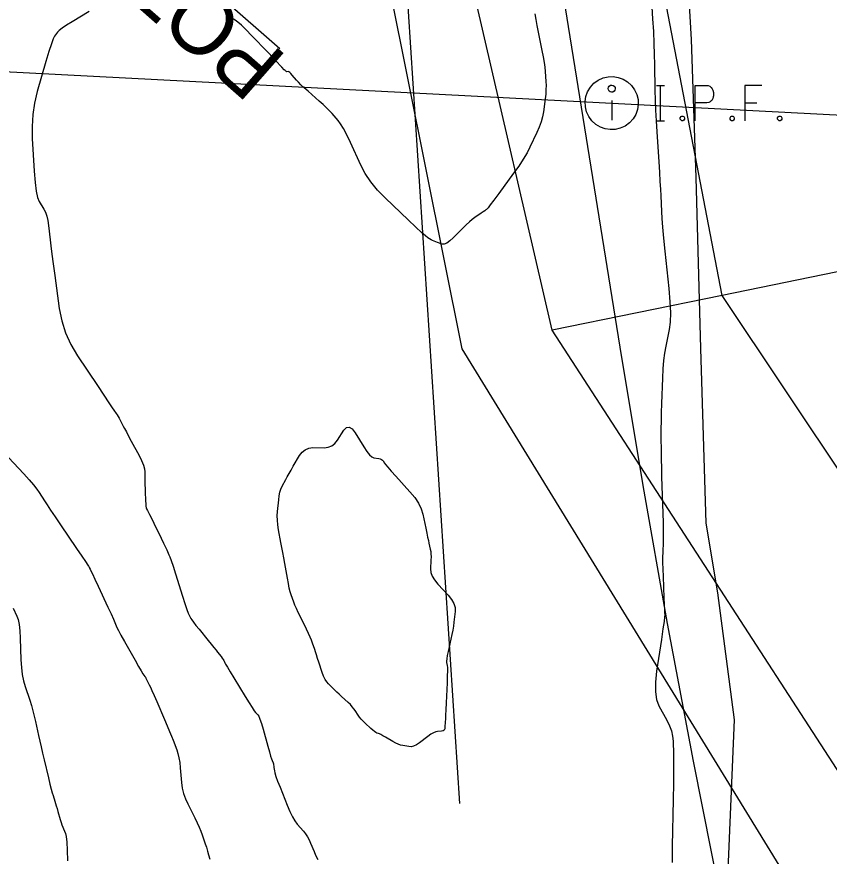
# Model space of a CAD drawing. Extents: x 2030588 to 2035216, y 462285 to 465007.
# Drawn here: x 2031207.57 to 2031244.28, y 464202.77 to 464240.7 of the extents above; entities that cross this region are included whole.
import ezdxf

# ---------------------------------------------------------------- set-up
doc = ezdxf.new("R2010")
doc.units = 0
for name, color, linetype in [('DT_P_Slope_Break_Line', 7, 'Continuous'), ('DT_X_Contour_Major', 7, 'Continuous'), ('DT_X_Contour_Minor', 7, 'Continuous'), ('DV_X_Property_Line', 7, 'Continuous'), ('GE_P_Alignment_100_Cardinal_Points', 7, 'Continuous'), ('MD_P_CONST_LIMITS', 7, 'Continuous'), ('RW_X_Esmt_SH', 7, 'Continuous'), ('SV_X_Break_Lines', 7, 'Continuous'), ('SV_X_Mon_Cells_Found', 7, 'Continuous'), ('VG_X_Tree_Line_Lt', 7, 'Continuous')]:
    doc.layers.add(name, color=color, linetype=linetype)

msp = doc.modelspace()

# ---------------------------------------------------------------- linework, layer by layer
at = {"layer": 'DT_P_Slope_Break_Line'}
for p, q in [((2031239.441, 464228.107), (2031234.605, 464253.315)), ((2031231.768, 464226.532), (2031225.918, 464251.764)), ((2031250.924, 464230.464), (2031239.441, 464228.107)), ((2031239.441, 464228.107), (2031231.768, 464226.532)), ((2031254.663, 464205.295), (2031239.441, 464228.107)), ((2031246.735, 464203.453), (2031231.768, 464226.532))]:
    msp.add_line(p, q, dxfattribs=at)
at = {"layer": 'DT_X_Contour_Major'}
msp.add_lwpolyline([(2031207.207, 464220.779), (2031207.892, 464220.039), (2031208.128, 464219.778), (2031208.322, 464219.552), (2031208.475, 464219.359), (2031208.587, 464219.2), (2031208.829, 464218.82), (2031208.942, 464218.646), (2031209.1, 464218.408), (2031209.302, 464218.106), (2031209.55, 464217.739), (2031210.269, 464216.677), (2031210.506, 464216.327), (2031210.676, 464216.076), (2031210.781, 464215.922), (2031210.819, 464215.866), (2031210.833, 464215.846), (2031210.839, 464215.837), (2031210.846, 464215.825), (2031210.855, 464215.808), (2031210.864, 464215.789), (2031210.892, 464215.731), (2031210.922, 464215.668), (2031210.991, 464215.521), (2031211.098, 464215.29), (2031211.245, 464214.976), (2031211.687, 464214.026), (2031211.833, 464213.711), (2031211.94, 464213.477), (2031212.008, 464213.325), (2031212.037, 464213.254), (2031212.063, 464213.173), (2031212.094, 464213.107), (2031212.167, 464212.969), (2031212.283, 464212.758), (2031212.441, 464212.475), (2031212.92, 464211.625), (2031213.079, 464211.343), (2031213.198, 464211.135), (2031213.277, 464211.001), (2031213.316, 464210.941), (2031213.366, 464210.88), (2031213.387, 464210.851), (2031213.412, 464210.81), (2031213.44, 464210.758), (2031213.472, 464210.694), (2031213.563, 464210.508), (2031213.61, 464210.408), (2031213.681, 464210.25), (2031213.777, 464210.033), (2031213.897, 464209.757), (2031214.252, 464208.941), (2031214.376, 464208.654), (2031214.482, 464208.403), (2031214.57, 464208.187), (2031214.639, 464208.008), (2031214.8, 464207.579), (2031214.856, 464207.407), (2031214.902, 464207.213), (2031214.938, 464206.997), (2031214.964, 464206.758), (2031215.02, 464206.093), (2031215.054, 464205.845), (2031215.111, 464205.601), (2031215.193, 464205.361), (2031215.299, 464205.125), (2031215.615, 464204.5), (2031215.725, 464204.276), (2031215.818, 464204.073), (2031215.894, 464203.89), (2031215.953, 464203.728), (2031216.089, 464203.323), (2031216.14, 464203.167), (2031216.19, 464202.999), (2031216.24, 464202.822), (2031216.29, 464202.634)], dxfattribs=at)
at = {"layer": 'DT_X_Contour_Minor'}
for points in [[(2031236.213, 464242.213), (2031236.306, 464240.613), (2031236.338, 464240.034), (2031236.363, 464239.496), (2031236.381, 464238.998), (2031236.391, 464238.542), (2031236.411, 464237.379), (2031236.422, 464236.934), (2031236.439, 464236.472), (2031236.463, 464235.993), (2031236.493, 464235.497), (2031236.582, 464234.15), (2031236.613, 464233.675), (2031236.638, 464233.26), (2031236.658, 464232.904), (2031236.673, 464232.609), (2031236.705, 464231.901), (2031236.723, 464231.589), (2031236.756, 464231.186), (2031236.802, 464230.69), (2031236.861, 464230.103), (2031237.038, 464228.415), (2031237.089, 464227.825), (2031237.108, 464227.321), (2031237.097, 464226.905), (2031237.053, 464226.575), (2031236.897, 464225.81), (2031236.843, 464225.505), (2031236.801, 464225.164), (2031236.769, 464224.786), (2031236.748, 464224.373), (2031236.707, 464223.222), (2031236.694, 464222.808), (2031236.686, 464222.428), (2031236.682, 464222.084), (2031236.683, 464221.775), (2031236.692, 464220.996), (2031236.697, 464220.683), (2031236.704, 464220.328), (2031236.714, 464219.931), (2031236.727, 464219.491), (2031236.765, 464218.261), (2031236.776, 464217.835), (2031236.782, 464217.479), (2031236.783, 464217.192), (2031236.779, 464216.976), (2031236.76, 464216.491), (2031236.756, 464216.287), (2031236.757, 464216.038), (2031236.764, 464215.743), (2031236.776, 464215.404), (2031236.816, 464214.44), (2031236.829, 464214.122), (2031236.84, 464213.892), (2031236.847, 464213.749), (2031236.851, 464213.693), (2031236.857, 464213.662), (2031236.849, 464213.584), (2031236.82, 464213.375), (2031236.77, 464213.035), (2031236.7, 464212.563), (2031236.485, 464211.13), (2031236.431, 464210.629), (2031236.431, 464210.201), (2031236.484, 464209.846), (2031236.591, 464209.563), (2031236.948, 464208.907), (2031237.065, 464208.664), (2031237.152, 464208.426), (2031237.207, 464208.194), (2031237.23, 464207.967), (2031237.251, 464207.37), (2031237.255, 464207.075), (2031237.254, 464206.637), (2031237.246, 464206.057), (2031237.232, 464205.333), (2031237.187, 464203.214), (2031237.185, 464202.479)], [(2031210.838, 464240.942), (2031210.082, 464240.475), (2031209.827, 464240.314), (2031209.632, 464240.181), (2031209.494, 464240.075), (2031209.415, 464239.997), (2031209.283, 464239.826), (2031209.221, 464239.707), (2031209.136, 464239.475), (2031209.026, 464239.132), (2031208.892, 464238.678), (2031208.502, 464237.318), (2031208.378, 464236.803), (2031208.299, 464236.277), (2031208.264, 464235.74), (2031208.274, 464235.192), (2031208.36, 464233.718), (2031208.398, 464233.218), (2031208.447, 464232.824), (2031208.509, 464232.536), (2031208.582, 464232.353), (2031208.793, 464232.007), (2031208.866, 464231.864), (2031208.926, 464231.692), (2031208.973, 464231.493), (2031209.008, 464231.266), (2031209.084, 464230.623), (2031209.119, 464230.341), (2031209.165, 464229.979), (2031209.223, 464229.537), (2031209.293, 464229.014), (2031209.495, 464227.513), (2031209.603, 464226.957), (2031209.777, 464226.416), (2031210.015, 464225.891), (2031210.319, 464225.381), (2031211.215, 464224.04), (2031211.514, 464223.593), (2031211.739, 464223.258), (2031211.889, 464223.034), (2031211.966, 464222.922), (2031212.07, 464222.773), (2031212.111, 464222.712), (2031212.154, 464222.641), (2031212.201, 464222.559), (2031212.25, 464222.466), (2031212.386, 464222.206), (2031212.447, 464222.09), (2031212.528, 464221.937), (2031212.629, 464221.748), (2031212.75, 464221.522), (2031213.1, 464220.87), (2031213.215, 464220.641), (2031213.297, 464220.441), (2031213.346, 464220.272), (2031213.363, 464220.132), (2031213.363, 464219.8), (2031213.364, 464219.671), (2031213.367, 464219.535), (2031213.37, 464219.392), (2031213.376, 464219.24), (2031213.391, 464218.826), (2031213.399, 464218.687), (2031213.409, 464218.579), (2031213.422, 464218.503), (2031213.438, 464218.459), (2031213.484, 464218.383), (2031213.514, 464218.326), (2031213.571, 464218.213), (2031213.654, 464218.044), (2031213.764, 464217.819), (2031214.092, 464217.144), (2031214.202, 464216.916), (2031214.288, 464216.738), (2031214.35, 464216.611), (2031214.387, 464216.533), (2031214.452, 464216.392), (2031214.488, 464216.299), (2031214.549, 464216.124), (2031214.633, 464215.867), (2031214.741, 464215.528), (2031215.061, 464214.517), (2031215.17, 464214.178), (2031215.256, 464213.921), (2031215.32, 464213.746), (2031215.361, 464213.652), (2031215.44, 464213.511), (2031215.485, 464213.441), (2031215.562, 464213.337), (2031215.67, 464213.198), (2031215.809, 464213.026), (2031216.223, 464212.519), (2031216.365, 464212.343), (2031216.484, 464212.196), (2031216.579, 464212.077), (2031216.65, 464211.987), (2031216.807, 464211.783), (2031216.86, 464211.713), (2031216.901, 464211.656), (2031216.931, 464211.611), (2031216.948, 464211.578), (2031216.978, 464211.508), (2031217.012, 464211.445), (2031217.092, 464211.31), (2031217.217, 464211.102), (2031217.387, 464210.822), (2031217.901, 464209.977), (2031218.074, 464209.695), (2031218.209, 464209.482), (2031218.305, 464209.339), (2031218.363, 464209.265), (2031218.466, 464209.161), (2031218.509, 464209.09), (2031218.563, 464208.958), (2031218.628, 464208.764), (2031218.703, 464208.508), (2031218.916, 464207.744), (2031218.988, 464207.488), (2031219.044, 464207.293), (2031219.084, 464207.16), (2031219.108, 464207.088), (2031219.152, 464206.98), (2031219.167, 464206.936), (2031219.179, 464206.888), (2031219.189, 464206.835), (2031219.196, 464206.778), (2031219.212, 464206.618), (2031219.232, 464206.527), (2031219.282, 464206.374), (2031219.361, 464206.161), (2031219.47, 464205.885), (2031219.797, 464205.069), (2031219.918, 464204.786), (2031220.034, 464204.55), (2031220.145, 464204.36), (2031220.251, 464204.216), (2031220.527, 464203.896), (2031220.625, 464203.772), (2031220.712, 464203.642), (2031220.788, 464203.505), (2031220.852, 464203.362), (2031221.007, 464202.971), (2031221.079, 464202.807), (2031221.178, 464202.61)], [(2031230.984, 464240.83), (2031231.022, 464240.574), (2031231.07, 464240.299), (2031231.129, 464240.002), (2031231.299, 464239.183), (2031231.356, 464238.893), (2031231.4, 464238.637), (2031231.432, 464238.416), (2031231.451, 464238.229), (2031231.484, 464237.776), (2031231.491, 464237.6), (2031231.487, 464237.411), (2031231.473, 464237.208), (2031231.449, 464236.993), (2031231.369, 464236.402), (2031231.328, 464236.177), (2031231.265, 464235.946), (2031231.181, 464235.708), (2031231.075, 464235.464), (2031230.763, 464234.803), (2031230.629, 464234.544), (2031230.461, 464234.261), (2031230.26, 464233.955), (2031230.025, 464233.626), (2031229.355, 464232.717), (2031229.133, 464232.418), (2031228.971, 464232.201), (2031228.869, 464232.067), (2031228.826, 464232.015), (2031228.792, 464231.988), (2031228.768, 464231.97), (2031228.72, 464231.936), (2031228.649, 464231.887), (2031228.554, 464231.821), (2031228.271, 464231.625), (2031228.157, 464231.54), (2031228.029, 464231.432), (2031227.886, 464231.302), (2031227.729, 464231.148), (2031227.29, 464230.708), (2031227.136, 464230.567), (2031227.002, 464230.473), (2031226.89, 464230.427), (2031226.798, 464230.429), (2031226.58, 464230.496), (2031226.502, 464230.523), (2031226.429, 464230.552), (2031226.361, 464230.584), (2031226.3, 464230.619), (2031226.143, 464230.716), (2031226.044, 464230.793), (2031225.863, 464230.953), (2031225.601, 464231.195), (2031225.257, 464231.52), (2031224.232, 464232.496), (2031223.874, 464232.864), (2031223.568, 464233.236), (2031223.315, 464233.612), (2031223.115, 464233.993), (2031222.649, 464235.013), (2031222.484, 464235.363), (2031222.336, 464235.646), (2031222.207, 464235.863), (2031222.095, 464236.013), (2031221.821, 464236.325), (2031221.708, 464236.448), (2031221.573, 464236.583), (2031221.416, 464236.731), (2031221.238, 464236.891), (2031220.734, 464237.335), (2031220.56, 464237.491), (2031220.415, 464237.626), (2031220.3, 464237.741), (2031220.214, 464237.834), (2031220.025, 464238.056), (2031219.96, 464238.129), (2031219.908, 464238.18), (2031219.868, 464238.211), (2031219.841, 464238.22), (2031219.784, 464238.216), (2031219.76, 464238.221), (2031219.731, 464238.237), (2031219.696, 464238.266), (2031219.657, 464238.306), (2031219.544, 464238.428), (2031219.473, 464238.504), (2031219.344, 464238.641), (2031219.157, 464238.837), (2031218.913, 464239.094), (2031218.183, 464239.859), (2031217.932, 464240.117), (2031217.725, 464240.317), (2031217.562, 464240.461), (2031217.444, 464240.546), (2031217.187, 464240.699), (2031217.073, 464240.755)], [(2031220.942, 464212.4), (2031220.898, 464212.521), (2031220.837, 464212.666), (2031220.759, 464212.836), (2031220.663, 464213.031), (2031220.387, 464213.583), (2031220.29, 464213.779), (2031220.209, 464213.955), (2031220.143, 464214.11), (2031220.092, 464214.243), (2031219.977, 464214.572), (2031219.933, 464214.711), (2031219.889, 464214.883), (2031219.845, 464215.087), (2031219.8, 464215.324), (2031219.68, 464215.999), (2031219.636, 464216.248), (2031219.593, 464216.488), (2031219.55, 464216.719), (2031219.51, 464216.941), (2031219.402, 464217.521), (2031219.369, 464217.736), (2031219.351, 464217.945), (2031219.347, 464218.148), (2031219.358, 464218.345), (2031219.408, 464218.863), (2031219.431, 464219.048), (2031219.466, 464219.212), (2031219.511, 464219.358), (2031219.567, 464219.483), (2031219.731, 464219.792), (2031219.798, 464219.916), (2031219.876, 464220.056), (2031219.966, 464220.213), (2031220.066, 464220.385), (2031220.348, 464220.867), (2031220.465, 464221.025), (2031220.604, 464221.137), (2031220.764, 464221.205), (2031220.946, 464221.228), (2031221.461, 464221.227), (2031221.643, 464221.248), (2031221.805, 464221.312), (2031221.945, 464221.418), (2031222.064, 464221.567), (2031222.354, 464222.02), (2031222.468, 464222.14), (2031222.591, 464222.158), (2031222.724, 464222.075), (2031222.866, 464221.891), (2031223.258, 464221.265), (2031223.397, 464221.058), (2031223.519, 464220.906), (2031223.625, 464220.81), (2031223.713, 464220.769), (2031223.928, 464220.734), (2031224.001, 464220.718), (2031224.059, 464220.695), (2031224.102, 464220.667), (2031224.131, 464220.633), (2031224.186, 464220.534), (2031224.234, 464220.469), (2031224.337, 464220.347), (2031224.494, 464220.169), (2031224.705, 464219.934), (2031225.34, 464219.232), (2031225.554, 464218.972), (2031225.722, 464218.718), (2031225.843, 464218.469), (2031225.917, 464218.226), (2031226.051, 464217.586), (2031226.099, 464217.363), (2031226.139, 464217.176), (2031226.172, 464217.025), (2031226.198, 464216.909), (2031226.26, 464216.647), (2031226.279, 464216.542), (2031226.289, 464216.424), (2031226.292, 464216.293), (2031226.287, 464216.149), (2031226.263, 464215.747), (2031226.277, 464215.591), (2031226.338, 464215.426), (2031226.445, 464215.251), (2031226.599, 464215.066), (2031227.072, 464214.561), (2031227.224, 464214.373), (2031227.327, 464214.188), (2031227.38, 464214.005), (2031227.384, 464213.825), (2031227.327, 464213.347), (2031227.303, 464213.164), (2031227.272, 464212.975), (2031227.235, 464212.778), (2031227.191, 464212.575), (2031227.066, 464212.023), (2031227.027, 464211.836), (2031227.002, 464211.688), (2031226.991, 464211.581), (2031226.995, 464211.513), (2031227.025, 464211.384), (2031227.033, 464211.3), (2031227.034, 464211.141), (2031227.029, 464210.91), (2031227.017, 464210.605), (2031226.976, 464209.694), (2031226.962, 464209.384), (2031226.951, 464209.137), (2031226.942, 464208.954), (2031226.936, 464208.833), (2031226.923, 464208.595), (2031226.91, 464208.516), (2031226.881, 464208.459), (2031226.835, 464208.424), (2031226.773, 464208.41), (2031226.585, 464208.401), (2031226.506, 464208.385), (2031226.408, 464208.343), (2031226.291, 464208.275), (2031226.155, 464208.181), (2031225.77, 464207.895), (2031225.631, 464207.804), (2031225.504, 464207.743), (2031225.388, 464207.714), (2031225.284, 464207.717), (2031225.022, 464207.764), (2031224.92, 464207.789), (2031224.811, 464207.828), (2031224.696, 464207.881), (2031224.573, 464207.947), (2031224.236, 464208.143), (2031224.122, 464208.208), (2031224.031, 464208.258), (2031223.964, 464208.291), (2031223.922, 464208.308), (2031223.839, 464208.333), (2031223.8, 464208.353), (2031223.743, 464208.394), (2031223.669, 464208.455), (2031223.577, 464208.537), (2031223.31, 464208.785), (2031223.216, 464208.876), (2031223.134, 464208.964), (2031223.064, 464209.05), (2031223.006, 464209.132), (2031222.868, 464209.348), (2031222.808, 464209.432), (2031222.734, 464209.52), (2031222.646, 464209.614), (2031222.543, 464209.713), (2031222.248, 464209.985), (2031222.141, 464210.083), (2031222.042, 464210.176), (2031221.951, 464210.263), (2031221.868, 464210.343), (2031221.656, 464210.551), (2031221.579, 464210.641), (2031221.508, 464210.756), (2031221.441, 464210.897), (2031221.38, 464211.062), (2031221.224, 464211.537), (2031221.168, 464211.707), (2031221.118, 464211.859), (2031221.074, 464211.994), (2031221.036, 464212.111), (2031220.942, 464212.4)], [(2031207.41, 464213.978), (2031207.582, 464213.619), (2031207.64, 464213.456), (2031207.685, 464213.235), (2031207.716, 464212.955), (2031207.734, 464212.618), (2031207.764, 464211.642), (2031207.784, 464211.292), (2031207.821, 464210.975), (2031207.875, 464210.691), (2031207.946, 464210.439), (2031208.158, 464209.811), (2031208.234, 464209.574), (2031208.303, 464209.337), (2031208.365, 464209.098), (2031208.42, 464208.858), (2031208.557, 464208.216), (2031208.611, 464207.967), (2031208.671, 464207.702), (2031208.736, 464207.42), (2031208.808, 464207.123), (2031209.005, 464206.308), (2031209.073, 464206.028), (2031209.131, 464205.801), (2031209.177, 464205.626), (2031209.212, 464205.504), (2031209.292, 464205.247), (2031209.323, 464205.146), (2031209.356, 464205.035), (2031209.393, 464204.914), (2031209.432, 464204.783), (2031209.54, 464204.421), (2031209.579, 464204.293), (2031209.617, 464204.18), (2031209.654, 464204.081), (2031209.689, 464203.997), (2031209.779, 464203.793), (2031209.81, 464203.658), (2031209.834, 464203.407), (2031209.851, 464203.038), (2031209.862, 464202.553)]]:
    msp.add_lwpolyline(points, dxfattribs=at)
at = {"layer": 'DV_X_Property_Line'}
msp.add_line((2031127.582, 464242.357), (2031264.413, 464235.242), dxfattribs=at)
at = {"layer": 'GE_P_Alignment_100_Cardinal_Points'}
msp.add_line((2031185.644, 464268.94), (2031219.463, 464239.26), dxfattribs=at)
at = {"layer": 'MD_P_CONST_LIMITS'}
msp.add_lwpolyline([(2031213.423, 464452.904), (2031204.569, 464426.156), (2031208.548, 464401.477), (2031212.527, 464376.798), (2031213.545, 464351.642), (2031212.78, 464331.262), (2031212.588, 464326.168), (2031200.6, 464313.585), (2031192.908, 464308.049), (2031189.455, 464298.429), (2031209.379, 464281.464), (2031213.118, 464275.067), (2031222.806, 464250.019), (2031227.688, 464225.695), (2031242.004, 464202.354), (2031261.7, 464180.872), (2031268.395, 464156.387), (2031275.973, 464131.824), (2031285.052, 464107.55), (2031291.211, 464093.27), (2031304.871, 464099.462)], dxfattribs=at)
at = {"layer": 'RW_X_Esmt_SH'}
msp.add_line((2031234.838, 464225.767), (2031163.098, 464671.689), dxfattribs=at)
msp.add_lwpolyline([(2031270.23, 464097.808), (2031267.91, 464103.703), (2031265.652, 464109.622), (2031263.457, 464115.564), (2031261.324, 464121.529), (2031259.254, 464127.516), (2031257.247, 464133.525), (2031255.303, 464139.554), (2031253.423, 464145.603), (2031251.606, 464151.672), (2031249.853, 464157.76), (2031248.165, 464163.865), (2031246.54, 464169.988), (2031244.98, 464176.128), (2031243.485, 464182.284), (2031242.054, 464188.455), (2031240.688, 464194.641), (2031239.387, 464200.841), (2031238.152, 464207.054), (2031236.982, 464213.28), (2031235.877, 464219.518), (2031234.838, 464225.767)], dxfattribs=at)
at = {"layer": 'SV_X_Break_Lines'}
msp.add_lwpolyline([(2031232.844, 464301.653), (2031232.689, 464300.622), (2031232.305, 464297.05), (2031231.366, 464289.882), (2031228.828, 464284.488), (2031228.324, 464282.446), (2031229.043, 464277.962), (2031230.364, 464276.047), (2031233.203, 464272.545), (2031234.089, 464270.527), (2031236.063, 464263.603), (2031235.609, 464260.828), (2031235.68, 464258.612), (2031236.788, 464250.976), (2031237.698, 464245.666), (2031238.054, 464239.677), (2031238.251, 464233.432), (2031238.47, 464225.709), (2031238.713, 464217.811), (2031239.232, 464214.663), (2031239.995, 464208.924), (2031239.694, 464201.794), (2031239.265, 464194.815)], dxfattribs=at)
at = {"layer": 'SV_X_Mon_Cells_Found'}
for p, q in [((2031236.487, 464237.599), (2031236.839, 464237.599)), ((2031236.663, 464235.999), (2031236.663, 464237.599)), ((2031234.456, 464236.916), (2031234.456, 464236.033)), ((2031240.477, 464236.818), (2031241.017, 464236.818)), ((2031236.487, 464235.999), (2031236.839, 464235.999))]:
    msp.add_line(p, q, dxfattribs=at)
for points in [[(2031238.228, 464235.999), (2031238.228, 464237.599), (2031238.757, 464237.599), (2031238.812, 464237.587), (2031238.889, 464237.561), (2031238.923, 464237.536), (2031238.956, 464237.511), (2031239, 464237.448), (2031239.033, 464237.385), (2031239.055, 464237.284), (2031239.055, 464237.133), (2031239.044, 464237.083), (2031239.022, 464237.007), (2031238.978, 464236.919), (2031238.933, 464236.881), (2031238.901, 464236.856), (2031238.845, 464236.831), (2031238.757, 464236.818), (2031238.228, 464236.818)], [(2031241.237, 464237.599), (2031240.477, 464237.599), (2031240.477, 464235.999)], [(2031237.622, 464236.214), (2031237.677, 464236.214), (2031237.71, 464236.188), (2031237.743, 464236.138), (2031237.743, 464236.075), (2031237.71, 464236.025), (2031237.677, 464235.999), (2031237.622, 464235.999), (2031237.589, 464236.025), (2031237.556, 464236.075), (2031237.556, 464236.138), (2031237.589, 464236.188), (2031237.622, 464236.214)], [(2031239.87, 464236.214), (2031239.925, 464236.214), (2031239.959, 464236.188), (2031239.992, 464236.138), (2031239.992, 464236.075), (2031239.959, 464236.025), (2031239.925, 464235.999), (2031239.87, 464235.999), (2031239.837, 464236.025), (2031239.804, 464236.075), (2031239.804, 464236.138), (2031239.837, 464236.188), (2031239.87, 464236.214)], [(2031242.02, 464236.214), (2031242.075, 464236.214), (2031242.108, 464236.188), (2031242.141, 464236.138), (2031242.141, 464236.075), (2031242.108, 464236.025), (2031242.075, 464235.999), (2031242.02, 464235.999), (2031241.986, 464236.025), (2031241.953, 464236.075), (2031241.953, 464236.138), (2031241.986, 464236.188), (2031242.02, 464236.214)]]:
    msp.add_lwpolyline(points, dxfattribs=at)
for centre, major_axis in [((2031234.456, 464236.799), (0.801, -0.894)), ((2031234.456, 464237.451), (0.107, -0.119))]:
    msp.add_ellipse(centre, major_axis=major_axis, ratio=0.999987, dxfattribs=at)
at = {"layer": 'VG_X_Tree_Line_Lt'}
msp.add_lwpolyline([(2031171.252, 464603.925), (2031180.58, 464539.236), (2031190.567, 464478.707), (2031195.183, 464442.795), (2031200.666, 464404.618), (2031207.96, 464347.776), (2031213.537, 464319.454), (2031224.286, 464260.057), (2031224.633, 464250.708), (2031227.583, 464205.148)], dxfattribs=at)

# ---------------------------------------------------------------- texts
at = {"layer": 'GE_P_Alignment_100_Cardinal_Points'}
msp.add_text('POT', height=2.7997, rotation=138.729, dxfattribs=at).set_placement((2031219.859, 464238.856))

doc.saveas('drawing.dxf')
